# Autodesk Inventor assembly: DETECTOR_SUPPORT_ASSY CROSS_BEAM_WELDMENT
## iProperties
Shininess: 64.0
Length Units: 11272
Angle Units: 11279
Time Units: 11290
Mass Units: 11286
Length Display Precision: 3
Angle Display Precision: 2
Compacted: True
Part Number: DETECTOR_SUPPORT_ASSY CROSS_BEAM_WELDMENT
Document SubType Name: Assembly
Created: 2004-08
Designer: John Blackburn
Manufacturer: Standard
Standards Organization: Custom
Density: 0.0
Volumn: 0.0
Area: 0.0
PropertySet Name: Model Information
Control State: 0
Master: False
Checked Out: False
Author: John Blackburn
